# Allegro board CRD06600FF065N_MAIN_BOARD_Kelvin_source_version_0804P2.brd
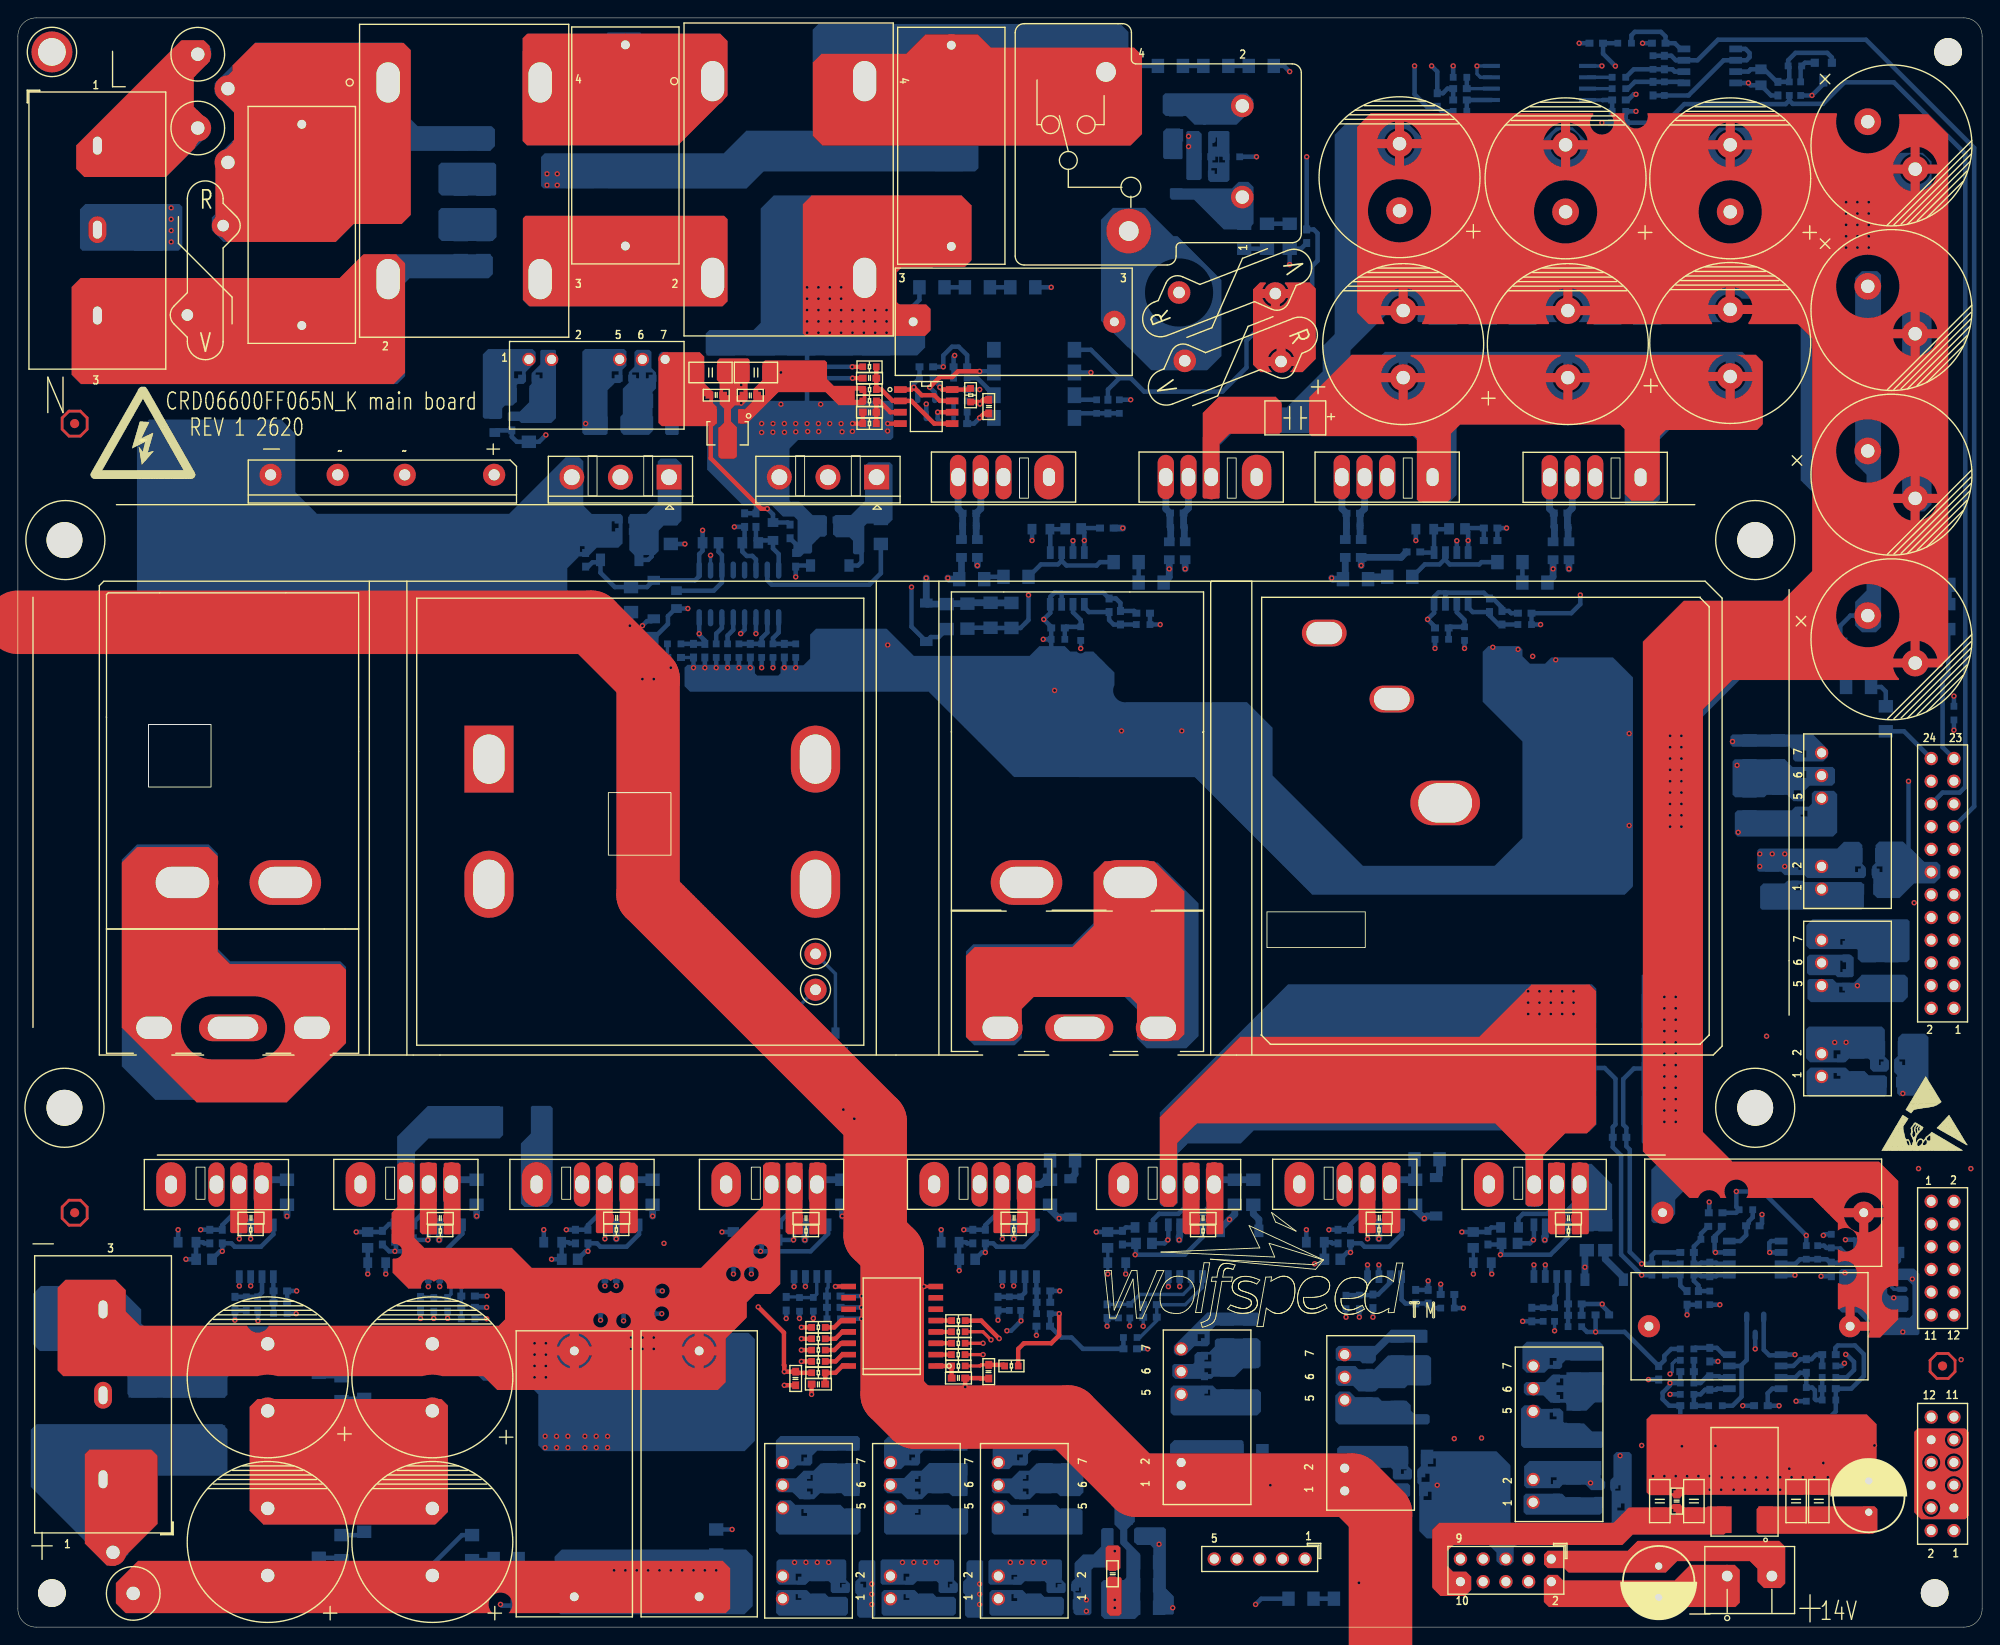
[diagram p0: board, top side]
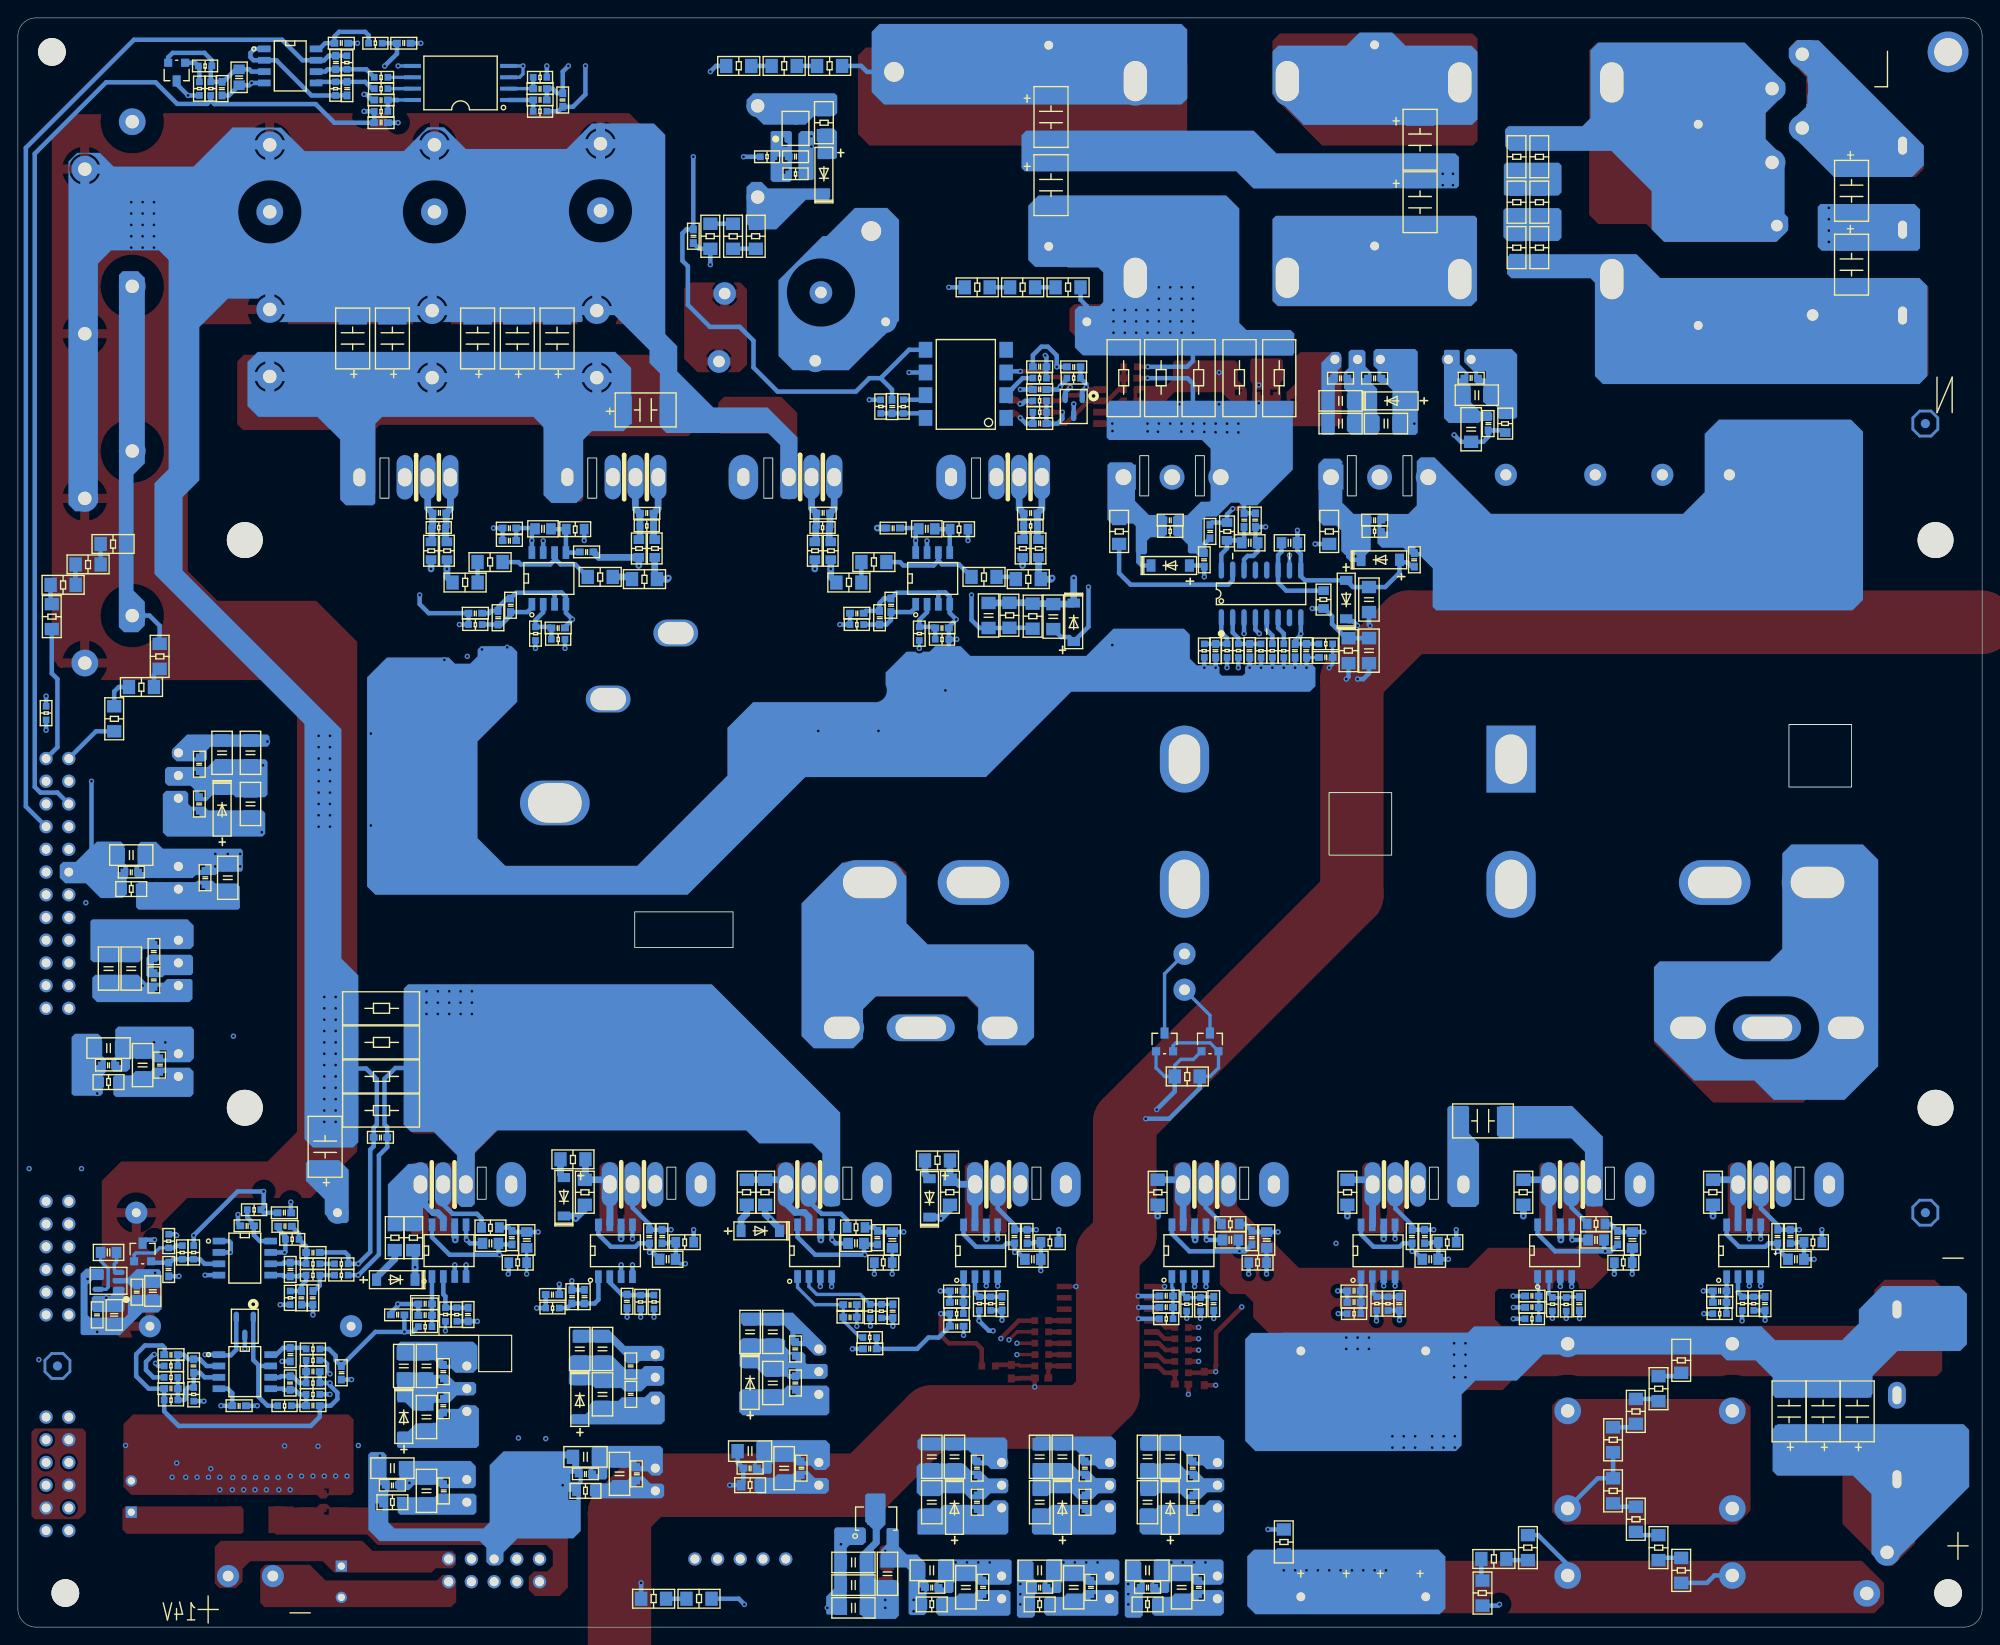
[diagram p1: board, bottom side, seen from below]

Outline 219.69 x 180 mm; copper layers: TOP, ART02, ART03, GND04, ART05, BOTTOM. Coordinates in mm from the lower left corner of the outline.
Outline path: rectangle 14.61,93.97 21.6,100.97 ; rectangle 19.93,47.85 20.93,51.45 ; rectangle 41.14,47.85 42.14,51.45 ; rectangle 60.82,47.85 61.82,51.45 ; rectangle 63.78,126.53 64.78,131.03 ; rectangle 66.04,86.35 73.04,93.34 ; rectangle 70,126.53 71,131.03 ; rectangle 82.03,47.85 83.03,51.45 ; rectangle 86.99,126.53 87.99,131.03 ; rectangle 93.21,126.53 94.21,131.03 ; rectangle 105.27,47.85 106.27,51.45 ; rectangle 112.02,126.27 113.02,130.77 ; rectangle 126.42,47.85 127.42,51.45 ; rectangle 135.26,126.27 136.26,130.77 ; rectangle 139.7,76.01 150.7,80.01 ; rectangle 146.1,47.85 147.1,51.45 ; rectangle 154.95,126.27 155.95,130.77 ; rectangle 167.31,47.85 168.31,51.45 ; rectangle 178.19,126.27 179.19,130.77 ; 0,177.97 arc(0.6,179.4) 2.03,180 217.66,180 arc(219.09,179.4) 219.69,177.97 219.69,2.03 arc(219.09,0.6) 217.66,0 2.03,0 arc(0.6,0.6) 0,2.03 0,177.97

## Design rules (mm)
net group CLAMPQ8: nets CLAMPQ8 DRVSA
net group N: nets N N15816850
net group N17259967: nets N17259967 N17259969
net group PFCDRVB: nets N17381677 PFCDRVB
net group PWM1B: nets N17750019 PWM1B
net group AC_L_SAMP: nets AC_L_SAMP AC_L_SAMP_D N17244938 N17244999
net group IPFC: nets IPFC N17245029 N17245032
net group N17259772: nets N17259772 N17259775 N17259778
net group PFC_G_A: nets N10486979 N16587331 N16587391 PFC_G_A

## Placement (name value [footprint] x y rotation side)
C1  0.1uF  [C0603]  144.15 155.57 90 bottom
C6  1n  [C0603]  149.35 124.59 0 bottom
C7  1n  [C0603]  172.55 124.61 0 bottom
C8  1n  [C0603]  90.81 123.83 180 bottom
C9  180uF  [ECAP_D18P7_5]  173.35 143.51 0 top
C10  180uF  [ECAP_D18P7_5]  154.53 162.18 0 top
C11  450V 180uF  [ECAP_D18P7_5]  173.1 162.05 0 top
C12  180uF  [ECAP_D18P7_5]  154.94 143.51 0 top
C13  180uF  [ECAP_D18P7_5]  209.55 110.49 225 top
C14  180uF  [ECAP_D18P7_5]  209.55 147.32 225 top
C15  180uF  [ECAP_D18P7_5]  191.52 162.05 0 top
C16  180uF  [ECAP_D18P7_5]  209.55 165.74 225 top
C17  180uF  [ECAP_D18P7_5]  209.55 128.91 225 top
C18  180uF  [ECAP_D18P7_5]  191.52 143.64 0 top
C23  1n  [C0603]  106.43 124.59 0 bottom
C24  1n  [C0603]  67.94 123.83 180 bottom
C25  1n  [C0603]  129.62 124.61 0 bottom
C26  0.1u  [C0603]  183.51 177.16 0 bottom
C27  0.1u  [C0603]  179.07 170.81 180 bottom
C28  DNP  [C0603]  182.88 172.09 90 bottom
C29  0.1u  [C0603]  161.29 170.81 0 bottom
C30  0.01u  [C0603]  161.29 172.09 180 bottom
C31  DNP  [C0603]  184.15 175.01 90 bottom
C33  2.2u  [C0805]  81.92 121.28 180 bottom
C34  10u  [C1206]  68.58 109.22 270 bottom
C35  0.33n  [C0603]  85.72 109.22 270 bottom
C36  0.33n  [C0603]  81.92 109.22 270 bottom
C37  10u  [C1206]  68.58 114.94 90 bottom
C38  2.2u  [C0805]  77.47 121.28 180 bottom
C39  1u  [C0603]  76.83 109.22 270 bottom
C40  0.1u  [C0603]  75.56 109.22 270 bottom
C41  2.2u  [C0805]  160.96 122.85 0 bottom
C42  10u  [C1206]  111.12 113.16 90 bottom
C43  0.33n  [C0603]  159.26 111.76 180 bottom
C44  0.33n  [C0603]  116.33 111.76 180 bottom
C45  10u  [C1206]  103.89 113.03 270 bottom
C46  2.2u  [C0805]  118.03 122.85 0 bottom
C47  1u  [C0603]  123.32 112.9 90 bottom
C48  0.1u  [C0603]  122.05 114.3 90 bottom
C53  1n  [C0603]  26.07 45.75 180 top
C54  1n  [C0603]  66.97 45.75 180 top
C55  470uF250V  [ECAP_D18P7_5]  27.94 9.53 0 top
C56  1n  [C0603]  111.42 45.75 180 top
C57  1n  [C0603]  152.26 45.75 180 top
C58  470uF250V  [ECAP_D18P7_5]  46.35 9.53 0 top
C59  0.1u  [C1812]  55.82 56.62 180 bottom
C63  5u  [CAPFILM_31_5X12_5MM]  62.23 17.14 90 top
C66  5u  [CAPFILM_31_5X12_5MM]  76.2 17.14 90 top
C72  470uF250V  [ECAP_D18P7_5]  27.94 27.94 0 top
C76  1n  [C0603]  47.24 45.72 180 top
C77  1n  [C0603]  88.15 45.72 180 top
C78  470uF250V  [ECAP_D18P7_5]  46.35 27.94 0 top
C79  1n  [C0603]  132.55 45.72 180 top
C80  1n  [C0603]  173.42 45.72 180 top
C81  1u  [C0603]  179.14 54.79 180 bottom
C82  0.47n  [C0603]  186.69 24.77 0 bottom
C83  0.12n  [C0603]  189.23 27.3 270 bottom
C84  0.1u  [C0603]  194.05 44.89 180 bottom
C87  0.12n  [C0603]  186.69 28.57 0 bottom
C88  0.1u  [C0603]  194.94 24.77 180 bottom
C89  2.2n  [C0603]  186.69 36.83 270 bottom
C90  nc  [C0603]  187.96 36.83 270 bottom
C91  0.12n  [C0603]  189.23 40.01 90 bottom
C92  0.12n  [C0603]  202.56 26.67 0 bottom
C93  1n  [C0603]  202.82 40.01 270 bottom
C94  0.12n  [C0603]  189.81 44.82 0 bottom
C96  nc  [C0603]  186.69 41.91 180 bottom
C97  0.12n  [C0603]  200.03 29.21 270 bottom
C99  0.47n  [C0603]  202.56 30.48 180 bottom
C100  0u1  [C0603]  87 27.81 270 top
C101  0u1  [C0603]  108.58 28.57 270 top
C102  0u1  [C0603]  105.2 27.85 180 top
C103  0u1  [C0603]  89.53 27.18 0 top
C136  1uF  [C0603]  204.47 75.56 270 bottom
C137  10uF  [C1206]  209.55 64.77 180 bottom
C138  1uF  [C0603]  209.55 62.87 180 bottom
C139  0u1  [C0603]  203.84 62.87 90 bottom
C140  2u2  [C1206]  205.74 62.87 90 bottom
C141  10uF  [C1206]  207.01 73.66 270 bottom
C142  1uF  [C0603]  204.47 72.39 270 bottom
C143  10uF  [C1206]  209.55 73.66 270 bottom
C144  10u  [C1206]  77.47 140.34 180 top
C145  1u  [C0603]  78.11 137.79 180 top
C146  1u  [C1206]  82.55 140.34 0 top
C147  1u  [C0603]  81.92 137.79 0 top
C148  1uF  [C0603]  199.39 96.52 270 bottom
C149  4u7  [C1206]  196.85 97.79 270 bottom
C150  10uF  [C1206]  193.68 97.79 270 bottom
C151  1uF  [C0603]  207.01 84.45 180 bottom
C152  0u1  [C0603]  198.75 83.82 90 bottom
C153  1uF  [C0603]  71.75 139.7 180 bottom
C154  4u7  [C1206]  71.75 137.16 180 bottom
C155  10uF  [C1206]  71.75 134.62 180 bottom
C156  10uF  [C1206]  57.15 133.99 90 bottom
C157  10uF  [C1206]  207.01 86.36 180 bottom
C158  1uF  [C0603]  55.24 134.62 90 bottom
C159  0u1  [C0603]  57.15 139.7 0 bottom
C160  2u2  [C1206]  56.52 137.79 0 bottom
C161  2u2  [C1206]  196.22 83.82 90 bottom
C162  1uF  [C0603]  199.39 92.08 270 bottom
C163  10uF  [C1206]  193.68 92.08 270 bottom
C164  1uF  [C0603]  67.94 139.7 180 bottom
C165  10uF  [C1206]  66.67 134.62 180 bottom
C166  1uF  [C0603]  132.72 31.11 270 bottom
C167  4u7  [C1206]  135.25 33.02 270 bottom
C168  10uF  [C1206]  137.79 33.02 270 bottom
C169  10uF  [C1206]  154.31 31.11 270 bottom
C170  1uF  [C0603]  137.79 17.78 180 bottom
C171  1uF  [C0603]  151.13 29.21 270 bottom
C172  4u7  [C1206]  156.84 31.11 270 bottom
C173  10uF  [C1206]  137.79 19.68 180 bottom
C174  0u1  [C0603]  132.08 17.78 90 bottom
C175  2u2  [C1206]  133.99 17.78 90 bottom
C176  1uF  [C0603]  172.09 28.57 270 bottom
C177  10uF  [C1206]  156.21 19.05 180 bottom
C178  1uF  [C0603]  156.21 17.14 180 bottom
C179  0u1  [C0603]  150.5 17.14 90 bottom
C180  2u2  [C1206]  152.4 17.14 90 bottom
C181  10uF  [C1206]  177.8 17.78 180 bottom
C182  1uF  [C0603]  177.8 15.88 180 bottom
C183  0u1  [C0603]  172.09 15.24 90 bottom
C184  2u2  [C1206]  173.99 15.24 90 bottom
C186  1uF  [C0603]  132.72 27.3 270 bottom
C187  1uF  [C0603]  151.13 26.04 270 bottom
C188  10uF  [C1206]  154.31 26.04 270 bottom
C189  1uF  [C0603]  172.09 24.77 270 bottom
C191  10uF  [C1206]  135.25 27.3 270 bottom
C192  1uF  [C0603]  88.27 17.78 270 bottom
C193  4u7  [C1206]  90.81 19.05 270 bottom
C194  10uF  [C1206]  93.34 19.05 270 bottom
C195  1uF  [C0603]  93.34 4.45 180 bottom
C196  0u1  [C0603]  87.63 4.45 90 bottom
C197  2u2  [C1206]  89.53 4.45 90 bottom
C198  1uF  [C0603]  100.33 17.78 270 bottom
C199  10uF  [C1206]  93.34 6.35 180 bottom
C200  4u7  [C1206]  102.87 19.05 270 bottom
C201  10uF  [C1206]  105.41 19.05 270 bottom
C202  1uF  [C0603]  88.27 13.97 270 bottom
C203  10uF  [C1206]  105.41 6.35 180 bottom
C204  1uF  [C0603]  105.41 4.45 180 bottom
C205  0u1  [C0603]  99.69 4.45 90 bottom
C206  1uF  [C0603]  112.39 17.78 270 bottom
C207  2u2  [C1206]  101.6 4.45 90 bottom
C209  10uF  [C1206]  93.34 13.97 270 bottom
C210  10uF  [C1206]  117.47 6.35 180 bottom
C211  1uF  [C0603]  117.47 4.45 180 bottom
C212  0u1  [C0603]  111.76 4.45 90 bottom
C213  2u2  [C1206]  113.67 4.45 90 bottom
C214  1uF  [C0603]  100.33 13.97 270 bottom
C215  10uF  [C1206]  105.41 13.97 270 bottom
C216  1uF  [C0603]  112.39 13.97 270 bottom
C234  10u  [C1206]  183.64 14.1 270 top
C235  1u  [C0603]  185.55 14.1 270 top
C236  10u  [C1206]  187.45 14.1 270 top
C237  10u  [C1206]  198.88 14.1 270 top
C238  10u  [C1206]  201.42 14.1 270 top
C241  0.1u  [C0603]  210.82 34.92 270 bottom
C242  2.2u  [C0805]  208.91 34.92 270 bottom
C245  2.2u  [C0805]  209.55 41.91 180 bottom
C246  2.2u  [C0805]  204.6 37.59 270 bottom
C247  0.1u  [C0603]  206.38 37.47 270 bottom
C248  0.1u  [C0603]  189.23 30.48 90 bottom
C256  10u  [C1206]  122.43 5.97 90 bottom
C257  1u  [C0603]  122.43 5.97 90 top
C258  1u  [C1206]  126.24 7.24 0 bottom
C260  22u  [C1206]  126.24 2.16 0 bottom
C261  22u  [C1206]  126.24 4.7 0 bottom
C267  0.1u  [C1812]  17.78 24.13 90 bottom
C268  0.1u  [C1812]  13.97 24.13 90 bottom
C269  0.1u  [C1812]  21.59 24.13 90 bottom
C270  0.1u  [C1812]  185.32 53.73 90 bottom
C271  0.1u  [C1812]  159.38 144.15 90 bottom
C272  0.1u  [C1812]  163.83 144.15 90 bottom
C273  0.1u  [C1812]  168.28 144.15 90 bottom
C274  0.1u  [C1812]  177.8 144.15 90 bottom
C275  0.1u  [C1812]  182.25 144.15 90 bottom
C276  0.1u  [C1812]  149.48 136.14 180 bottom
C277  0.1u  [C1812]  142.88 135.25 180 top
C278  0.1n  [C0603]  95.25 135.89 0 top
C279  0.1u  [C0603]  105.41 138.43 0 bottom
C280  0.1n  [C0603]  105.41 134.62 0 bottom
C281  220p  [C0603]  95.25 139.7 180 top
C282  4.7n  [C0603]  101.6 140.97 180 bottom
C284  1n  [C0603]  132.72 164.47 0 bottom
C478  1n  [C0603]  196.85 172.09 270 bottom
C479  10uF  [C1206]  173.99 23.5 270 bottom
C480  10uF  [C1206]  176.53 29.21 270 bottom
C481  4u7  [C1206]  173.99 29.21 270 bottom
C482  10uF  [C1206]  117.47 19.05 270 bottom
C483  10uF  [C1206]  117.47 13.97 270 bottom
C484  4u7  [C1206]  114.94 19.05 270 bottom
C496  1u  [C0603]  81.28 123.83 270 bottom
C497  1u  [C0603]  82.55 123.83 90 bottom
C498  1u  [C0603]  156.08 120.27 180 bottom
C499  1u  [C0603]  164.72 121.54 180 bottom
C524  1u  [C0603]  87 119.38 270 bottom
C525  1u  [C0603]  63.5 119.38 270 bottom
C530  0.1u  [C0603]  164.59 114.3 90 bottom
C531  1u  [C0603]  165.99 112.9 90 bottom
C532  0.1u  [C0603]  114.7 37.6 0 bottom
C533  1u  [C0603]  114.7 36.33 0 bottom
C536  1u  [C0603]  106.81 43.69 90 bottom
C537  1u  [C0603]  108.2 43.69 270 bottom
C540  0.1u  [C0603]  126.62 36.07 180 bottom
C541  1u  [C0603]  126.62 34.67 180 bottom
C542  2.2u  [C0805]  106.17 41.15 0 bottom
C543  0.33n  [C0603]  121.82 35.34 270 bottom
C544  0.33n  [C0603]  109.62 36.18 270 bottom
C545  2.2u  [C0805]  121.88 43.31 90 bottom
C547  1u  [C0603]  123.54 43.56 270 bottom
C549  2.2u  [C0805]  125.95 42.93 180 bottom
C550  0.1u  [C0603]  156.34 36.96 90 bottom
C551  1u  [C0603]  157.73 36.96 90 bottom
C552  1u  [C0603]  149.05 43.69 270 bottom
C553  1u  [C0603]  147.65 43.69 90 bottom
C554  0.1u  [C0603]  174.14 36.15 0 bottom
C555  1u  [C0603]  174.14 34.88 0 bottom
C556  2.2u  [C0805]  147.02 41.15 0 bottom
C557  0.33n  [C0603]  169.33 34.96 270 bottom
C558  0.33n  [C0603]  151.55 36.44 270 bottom
C559  2.2u  [C0805]  162.77 43.31 90 bottom
C561  1u  [C0603]  164.42 43.56 270 bottom
C563  2.2u  [C0805]  166.84 42.93 180 bottom
C564  0.1u  [C0603]  29.36 37.6 0 bottom
C565  1u  [C0603]  29.36 36.33 0 bottom
C566  1u  [C0603]  22.86 43.69 270 bottom
C567  1u  [C0603]  21.46 43.69 90 bottom
C568  0.1u  [C0603]  50.35 37.03 0 bottom
C569  1u  [C0603]  50.35 35.76 0 bottom
C570  2.2u  [C0805]  20.83 41.15 0 bottom
C571  0.33n  [C0603]  45.03 36.18 270 bottom
C572  0.33n  [C0603]  24.28 36.18 270 bottom
C573  2.2u  [C0805]  39.12 43.31 90 bottom
C575  1u  [C0603]  40.77 43.56 270 bottom
C577  2.2u  [C0805]  43.18 43.31 180 bottom
C578  0.1u  [C0603]  70.25 37.6 0 bottom
C579  1u  [C0603]  70.25 36.33 0 bottom
C580  1u  [C0603]  63.75 43.69 270 bottom
C581  1u  [C0603]  62.36 43.69 90 bottom
C582  0.1u  [C0603]  91.25 37.03 0 bottom
C583  1u  [C0603]  91.25 35.76 0 bottom
C584  2.2u  [C0805]  61.72 41.15 0 bottom
C585  0.33n  [C0603]  85.93 36.18 270 bottom
C586  0.33n  [C0603]  65.17 36.18 270 bottom
C587  2.2u  [C0805]  80.02 43.31 90 bottom
C589  1u  [C0603]  81.67 43.56 270 bottom
C591  2.2u  [C0805]  84.08 43.31 180 bottom
C592  2.2u  [C0805]  194.94 173.35 270 bottom
C593  25V 220uF  [ECAP_D8P3_5]  183.51 5.08 270 top
C594  25V 220uF  [ECAP_D8P3_5]  207.01 14.61 90 top
C595  2.2u  [C0603]  176.53 177.16 0 bottom
C596  2.2u  [C0603]  158.75 170.81 270 bottom
C597  2.2u  [C0603]  179.07 168.28 0 bottom
C598  2.2u  [C0603]  73.41 108.46 0 bottom
C599  2.2u  [C0603]  86.36 122.56 90 bottom
C601  2.2u  [C0603]  168.53 113.41 180 bottom
C602  2.2u  [C0603]  125.86 113.41 180 bottom
C603  2.2u  [C0603]  183.51 28.45 90 bottom
C604  2.2u  [C0603]  189.88 46.34 0 bottom
C605  2.2u  [C0603]  114.68 33.66 180 bottom
C606  2.2u  [C0603]  124.41 31.12 0 bottom
C607  2.2u  [C0603]  159.89 37.21 180 bottom
C608  2.2u  [C0603]  177.22 34.92 0 bottom
C610  2.2u  [C0603]  108.58 136.53 90 top
C611  2.2u  [C0603]  105.41 140.97 0 bottom
C612  0.1u  [C0603]  121.92 136.53 90 bottom
C613  1u  [C0603]  164.72 122.94 180 bottom
C614  1u  [C0603]  121.79 122.94 180 bottom
CB6  450V4u7  [CAPFILM_26_5X12MM]  195.2 46.35 0 top
CB7  450V4u7  [CAPFILM_26_5X12MM]  193.68 33.66 0 top
CL1  6Ts  [CM_4P]  49.91 161.78 270 top
CL2  6Ts  [CM_4P]  86.2 161.93 270 top
CON1  CON3  [KF45-3]  8.89 156.21 180 top
CON2  CON3  [KF45-3]  9.53 26.04 0 top
CT11  T1T2  [TH47_CR98]  89.21 71.29 0 top
CT12  T1T2  [TH47_CR98]  89.21 75.3 0 top
D1  1N4148W  [SOD-123]  129.54 162.56 270 bottom
D2  PB3510-E3/45  [PB3510]  40.77 128.14 180 top
D8  BAW56LT1  [SOT23]  194.31 33.66 0 bottom
D47  SBD  [SOD-123]  67.31 119.38 0 bottom
D48  SBD  [SOD-123]  90.81 118.75 0 bottom
D57  SBD  [SOD-123]  117.73 48.01 270 bottom
D58  SBD  [SOD-123]  158.62 48.13 270 bottom
D59  SBD  [SOD-123]  136.65 44.32 180 bottom
D60  SBD  [SOD-123]  177.42 38.86 180 bottom
D61  BAT754S  [SOT-23]  91.44 65.41 180 bottom
D62  BAT754S  [SOT-23]  86.36 65.41 180 bottom
F1  25A  [FULSE]  23.5 172.09 90 top
F2  25A  [FULSE]  23.5 163.83 90 top
F3  25A  [FULSE]  10.64 8.36 255 top
J3  CON24A  [CON_2MM54_12X2]  215.26 83.19 90 top
J4  CON12A  [CON_2MM54_6X2]  215.26 17.14 90 top
J5  CON12A  [CON_2MM54_6X2]  215.26 41.27 270 top
J6  CON2  [CON_5MM_2X1]  193.68 5.71 0 top
J7  CON10A  [CON_2MM54_5X2]  166.43 6.35 180 top
J8  CON5  [CON_2MM54_5X1]  138.89 7.62 180 top
MH1  T1T2  [MTH122]  3.81 176.19 0 top
NOREF  -  []  155.6 33.38 0 top
NOREF#2  #VAL  [unnamed#2]  215.26 29.21 0 top
NOREF#3  #VAL  [unnamed#3]  215.88 176.19 0 top
NOREF#4  #VAL  [unnamed#3]  3.81 3.81 0 top
NOREF#5  -  []  0 3.85 0 top
NOREF#6  -  []  3.99 0 90 top
NOREF#7  #VAL  [unnamed#2]  6.35 134.62 0 top
NOREF#8  -  []  13.97 132.72 0 top
NOREF#9  #VAL  [unnamed#2]  6.35 46.35 0 top
NOREF#10  -  []  0 3.24 0 top
NOREF#11  #VAL  [unnamed#3]  214.38 3.81 0 top
NOREF#12  -  []  18.45 0 90 top
NOREF#13  -  []  213.36 56.52 0 top
NOREF#14  #VAL  [unnamed#2]  215.26 29.21 180 bottom
NOREF#15  #VAL  [unnamed#2]  6.35 134.62 180 bottom
NOREF#16  #VAL  [unnamed#2]  6.35 46.35 180 bottom
Q2  C3M0060065K  [TO-247-4L]  153.15 128.63 180 top
Q3  C3M0060065K  [TO-247-4L]  176.41 128.61 180 top
Q4  C3M0060065D  [TO247]  90.6 128.63 180 top
Q5  C3M0060065D  [TO247]  67.39 128.63 180 top
Q6  C3M0060065K  [TO-247-4L]  110.24 128.64 180 top
Q7  C3M0060065K  [TO-247-4L]  133.46 128.64 180 top
Q8  C3M0060065K  [TO-247-4L]  22.2 49.5 0 top
Q9  C3M0060065K  [TO-247-4L]  63.09 49.52 0 top
Q10  C3M0060065K  [TO-247-4L]  107.56 49.53 0 top
Q11  C3M0060065K  [TO-247-4L]  148.4 49.53 0 top
Q12  C3M0060065K  [TO-247-4L]  43.39 49.52 0 top
Q13  C3M0060065K  [TO-247-4L]  84.29 49.52 0 top
Q14  C3M0060065K  [TO-247-4L]  128.7 49.52 0 top
Q15  C3M0060065K  [TO-247-4L]  169.59 49.52 0 top
Q60  FMMT718/SOT  [SOT23]  101.6 136.53 0 bottom
Q61  FMMT618/SOT  [SOT23]  132.72 167.64 180 bottom
R1  15R  [R1206]  137.16 155.57 270 bottom
R2  15R  [R1206]  139.7 155.57 90 bottom
R3  15R  [R1206]  142.24 155.57 270 bottom
R4  22  [R1206]  129.54 168.28 90 bottom
R5  1K  [R0603]  135.89 164.47 0 bottom
R6  360K  [R1206]  52.07 164.47 90 bottom
R7  360K  [R1206]  49.53 164.47 90 bottom
R8  10k  [R0603]  132.72 162.56 180 bottom
R9  360K  [R1206]  52.07 159.38 90 bottom
R10  360K  [R1206]  49.53 159.38 90 bottom
R11  360K  [R1206]  49.53 154.31 90 bottom
R12  360K  [R1206]  52.07 154.31 90 bottom
R14  1M  [R1206]  128.91 174.62 0 bottom
R15  1M  [R1206]  133.99 174.62 0 bottom
R16  1M  [R1206]  139.06 174.62 0 bottom
R20  1M  [R1206]  102.23 149.86 0 bottom
R21  1M  [R1206]  107.31 149.86 0 bottom
R22  1M  [R1206]  112.39 149.86 0 bottom
R27  5.6R  [R1206]  154.56 117.47 180 bottom
R28  5.6R  [R1206]  166.88 119.13 0 bottom
R29  100R  [R1206]  96.52 122.56 90 bottom
R30  0R  [R1206]  209.04 121.16 180 bottom
R31  10k  [R0603]  149.35 123.19 180 bottom
R32  10k  [R0603]  172.62 123 180 bottom
R33  10k  [R0603]  90.81 122.56 0 bottom
R34  1R  [R0805]  150.24 120.65 90 bottom
R35  1R  [R0805]  173.48 120.4 90 bottom
R37  470K  [R1206]  211.84 118.87 180 bottom
R38  470K  [R1206]  203.84 108.58 90 bottom
R39  470K  [R1206]  214.63 116.59 180 bottom
R40  470K  [R1206]  205.87 105.16 180 bottom
R41  8m  [R2512]  96.01 139.7 270 bottom
R42  8m  [R2512]  91.82 139.7 270 bottom
R43  470K  [R1206]  215.9 113.03 90 bottom
R44  8m  [R2512]  87.63 139.7 270 bottom
R45  470K  [R1206]  208.91 101.6 90 bottom
R46  8m  [R2512]  83.06 139.7 270 bottom
R47  8m  [R2512]  78.61 139.7 270 bottom
R48  100R  [R1206]  73.03 122.56 90 bottom
R51  5.6R  [R1206]  111.63 117.47 180 bottom
R52  5.6R  [R1206]  123.95 119.13 0 bottom
R53  10k  [R0603]  106.43 123.19 180 bottom
R54  10k  [R0603]  67.94 122.56 0 bottom
R55  10k  [R0603]  129.69 123 180 bottom
R56  1R  [R0805]  107.31 120.65 90 bottom
R60  1R  [R0805]  130.56 120.4 90 bottom
R62  68R  [R0603]  161.29 173.35 180 bottom
R63  2.4k  [R0603]  179.07 172.09 180 bottom
R64  2.4k  [R0603]  179.07 173.35 180 bottom
R65  3.3k  [R0603]  182.88 175.01 270 bottom
R66  3.3k  [R1206]  70.87 109.22 270 bottom
R67  4.7K  [R0603]  87 109.22 270 bottom
R68  4.7K  [R0603]  80.64 109.22 270 bottom
R69  1K  [R0603]  79.38 109.22 270 bottom
R70  NC  [R0603]  78.11 109.22 270 bottom
R71  100  [R0603]  161.8 111.12 90 bottom
R72  4.7K  [R0603]  159.26 110.49 180 bottom
R73  4.7K  [R0603]  116.33 110.49 180 bottom
R74  100  [R0603]  118.87 111.12 90 bottom
R75  2.2k  [R1206]  108.79 113.18 90 bottom
R78  10R  [R1206]  30.1 48.64 270 bottom
R79  10R  [R1206]  70.99 48.64 90 bottom
R80  10R  [R1206]  115.44 48.64 270 bottom
R81  10R  [R1206]  156.29 48.64 90 bottom
R82  10k  [R0603]  26.04 44.45 0 top
R83  10k  [R0603]  66.93 44.45 0 top
R84  510k  [R1206]  33.66 6.35 90 bottom
R85  10k  [R0603]  111.38 44.45 0 top
R86  10k  [R0603]  152.22 44.45 0 top
R89  510k  [R1206]  36.2 8.89 90 bottom
R90  510k  [R1206]  38.73 12.06 90 bottom
R93  510k  [R1206]  41.27 15.24 90 bottom
R94  9R1  [R1206]  51.31 48.64 270 bottom
R95  9R1  [R1206]  92.21 48.64 90 bottom
R96  510k  [R1206]  41.27 20.95 90 bottom
R97  9R1  [R1206]  136.11 48.64 270 bottom
R98  9R1  [R1206]  175.47 43.56 90 bottom
R99  10k  [R0603]  47.24 44.32 0 top
R100  10k  [R0603]  88.15 44.32 0 top
R101  510k  [R1206]  38.73 24.13 90 bottom
R102  510k  [R1206]  36.2 26.67 90 bottom
R103  10k  [R0603]  132.55 44.32 0 top
R104  10k  [R0603]  173.42 44.32 0 top
R107  510k  [R1206]  33.66 29.84 90 bottom
R110  20m  [R2512]  179.07 61.59 0 bottom
R111  20m  [R2512]  179.07 57.78 0 bottom
R112  20m  [R2512]  179.07 65.41 0 bottom
R113  20m  [R2512]  179.07 69.22 0 bottom
R114  470k  [R1206]  78.11 9.53 90 bottom
R115  470k  [R1206]  143.51 3.17 0 bottom
R116  100K  [R0603]  189.87 24.77 180 bottom
R117  1K  [R0603]  186.69 26.04 180 bottom
R118  470k  [R1206]  148.59 3.17 0 bottom
R119  47K  [R0603]  189.23 36.83 90 bottom
R120  1K  [R0603]  183.51 39.37 180 bottom
R121  5.6K  [R0603]  186.69 39.37 180 bottom
R122  15K  [R0603]  186.69 29.84 180 bottom
R123  1.2K  [R0603]  186.69 27.3 180 bottom
R126  200R  [R0603]  200.03 41.91 270 bottom
R127  100K  [R0603]  202.56 27.94 180 bottom
R128  1K  [R0603]  201.29 41.91 270 bottom
R129  1.2K  [R0603]  202.56 25.4 180 bottom
R130  5.6K  [R0603]  186.69 40.64 180 bottom
R132  47K  [R0603]  189.01 43.37 0 bottom
R134  15K  [R0603]  200.03 26.04 270 bottom
R135  1K  [R0603]  183.51 40.64 180 bottom
R136  3.57K  [R0603]  202.82 43.18 270 bottom
R138  1K  [R0603]  202.56 29.21 0 bottom
R139  10R  [R0603]  89.53 28.45 180 top
R140  10R  [R0603]  105.19 29.21 0 top
R141  51R  [R0603]  105.17 30.48 0 top
R142  51R  [R0603]  89.53 29.72 180 top
R143  51R  [R0603]  105.18 31.76 0 top
R144  51R  [R0603]  89.53 30.99 180 top
R145  51R  [R0603]  105.18 33.03 0 top
R146  51R  [R0603]  89.53 32.26 180 top
R147  51R  [R0603]  105.19 34.28 0 top
R148  51R  [R0603]  89.53 33.53 180 top
R181  1R  [R0805]  209.55 60.96 0 bottom
R182  1R  [R0805]  207.01 82.55 0 bottom
R183  1R  [R0805]  53.34 134.62 270 bottom
R184  1R  [R0805]  137.79 15.88 0 bottom
R185  1R  [R0805]  156.21 15.24 0 bottom
R186  1R  [R0805]  177.8 13.97 0 bottom
R187  1R  [R0805]  93.34 2.54 0 bottom
R188  1R  [R0805]  105.41 2.54 0 bottom
R189  1R  [R0805]  117.47 2.54 0 bottom
R216  BEAD  [R1206]  149.61 117.22 180 bottom
R217  BEAD  [R1206]  169.67 116.84 0 bottom
R218  BEAD  [R1206]  126.75 116.84 0 bottom
R219  BEAD  [R1206]  106.68 117.22 180 bottom
R234  DNP  [R1206]  106.2 113.08 90 bottom
R239  1K  [R0603]  101.6 139.7 0 bottom
R240  1.3K  [R0603]  95.25 137.16 180 top
R241  2K  [R0603]  105.41 135.89 180 bottom
R242  720R  [R0603]  105.41 137.16 0 bottom
R243  2K  [R0603]  95.25 134.62 180 top
R244  1K  [R0603]  95.25 140.97 180 top
R245  10k  [R0603]  95.25 138.43 0 top
R246  330R  [R0603]  105.41 139.7 0 bottom
R247  NC  [R0603]  120.65 136.53 270 bottom
R248  100  [R0603]  216.53 102.23 90 bottom
R250  100  [R0603]  83.19 109.22 90 bottom
R251  100  [R0603]  84.45 109.22 90 bottom
R537  3.3k  [R0603]  184.15 172.09 270 bottom
R538  1K  [R0603]  198.75 174.62 180 bottom
R539  3.57K  [R0603]  199.39 172.09 90 bottom
R540  200R  [R0603]  198.12 172.09 90 bottom
R541  1R  [R0805]  125.95 44.7 0 bottom
R542  1R  [R0805]  166.84 44.7 180 bottom
R543  1R  [R0805]  43.18 45.09 0 bottom
R544  1R  [R0805]  84.08 45.09 180 bottom
R545  10R  [R0603]  111.12 29.21 180 top
R548  4.7K  [R0603]  123.09 35.34 270 bottom
R549  200  [R0603]  124.36 35.34 90 bottom
R550  4.7K  [R0603]  110.89 36.18 270 bottom
R551  200  [R0603]  112.16 36.18 90 bottom
R552  4.7K  [R0603]  170.6 34.96 270 bottom
R553  200  [R0603]  171.87 34.96 90 bottom
R554  4.7K  [R0603]  150.04 36.38 270 bottom
R555  200  [R0603]  148.54 36.37 90 bottom
R556  4.7K  [R0603]  46.52 36.1 270 bottom
R557  200  [R0603]  48.06 36.11 90 bottom
R558  4.7K  [R0603]  25.55 36.18 270 bottom
R559  200  [R0603]  26.82 36.18 90 bottom
R560  4.7K  [R0603]  87.42 36.1 270 bottom
R561  200  [R0603]  88.97 36.11 90 bottom
R562  200  [R0603]  67.71 36.18 90 bottom
R563  4.7K  [R0603]  66.44 36.18 270 bottom
R564  4.3R  [R1206]  116.84 52.2 0 bottom
R565  4.3R  [R1206]  157.61 52.32 180 bottom
R566  3.6R  [R1206]  138.18 48.64 270 bottom
R567  3.6R  [R1206]  177.54 43.56 90 bottom
R568  NC  [R1206]  88.9 61.59 180 bottom
R569  470k  [R1206]  54.61 7.62 0 bottom
R570  470k  [R1206]  55.88 3.81 270 bottom
R571  470k  [R1206]  50.8 8.89 270 bottom
R572  10R  [R0603]  179.71 177.16 0 bottom
R573  10R  [R0603]  161.29 169.54 0 bottom
R574  10R  [R0603]  179.07 169.54 180 bottom
R575  10R  [R0603]  73.41 109.98 0 bottom
R576  10R  [R0805]  84.45 122.56 90 bottom
R577  10R  [R0805]  73.66 114.94 270 bottom
R578  10R  [R0603]  168.53 112.14 180 bottom
R579  10R  [R0603]  125.86 112.14 180 bottom
R580  1R  [R0805]  157.35 122.81 180 bottom
R581  1R  [R0805]  114.43 122.81 180 bottom
R582  10R  [R0603]  186.69 31.11 180 bottom
R583  10R  [R0603]  193.27 46.69 180 bottom
R584  10R  [R0603]  114.7 35.06 180 bottom
R585  10R  [R0603]  124.41 32.39 0 bottom
R586  10R  [R0603]  159.89 35.69 180 bottom
R587  10R  [R0603]  174.14 33.61 180 bottom
R588  1R  [R0805]  163.79 40.77 0 bottom
R589  1R  [R0805]  145.11 43.05 180 bottom
R590  1R  [R0805]  122.9 40.77 0 bottom
R591  1R  [R0805]  104.27 43.05 180 bottom
R592  1R  [R0805]  18.92 43.05 180 bottom
R593  1R  [R0805]  40.13 40.77 0 bottom
R594  1R  [R0805]  59.82 43.05 180 bottom
R595  1R  [R0805]  81.03 40.77 0 bottom
R596  10R  [R0603]  106.55 137.79 90 top
R597  10R  [R0603]  123.19 136.53 90 bottom
R598  10R  [R0603]  29.36 35.06 180 bottom
R599  10R  [R0603]  50.35 34.49 180 bottom
R600  10R  [R0603]  70.25 35.06 180 bottom
R601  10R  [R0603]  91.25 34.49 180 bottom
R602  2.2R  [R0805]  148.46 120.65 90 bottom
R603  2.2R  [R0805]  128.78 120.4 90 bottom
R604  2.2R  [R0805]  171.7 120.4 90 bottom
R605  2.2R  [R0805]  105.54 120.65 90 bottom
RLY1  832HA-1A-F-C-12VDC  [T9SV1K15-12]  129.32 165.06 90 top
RV1  NTC  [NTC_OD20MM]  135.25 149.22 201.2 top
RV2  NTC  [NTC_OD20MM]  135.89 141.6 21.4 top
T1  HEATSINK including PFC choke, Transformer and resonant tanks of CLLC  [HEATSINK20]  194.31 58.09 180 top
U2  OPA2376  [SOIC8]  189.23 174.62 180 bottom
U3  LM2904  [SOIC8]  194.31 28.57 180 bottom
U4  OPA2376  [SOIC8]  194.31 41.27 180 bottom
U5  SI8233BB-D-IS1  [SOIC16-127W]  80.64 115.57 90 bottom
U9  AZ431  1.25V  [SOT-23]  205.74 41.91 180 bottom
U10  Si8662  [WB_SOIC16]  97.79 33.66 90 top
U15  R15P21503D  [G1212S_2W11]  203.84 69.22 90 top
U16  MC78L05F-TP  [SOT-89-3L]  79.38 133.99 270 top
U17  R15P21503D  [G1212S_2W11]  203.84 90.17 90 top
U18  R15P21503D  [G1212S_2W11]  64.77 139.7 0 top
U19  R15P21503D  [G1212S_2W11]  132.21 23.5 90 top
U20  R15P21503D  [G1212S_2W11]  150.5 22.86 90 top
U21  R15P21503D  [G1212S_2W11]  171.58 21.59 90 top
U22  R15P21503D  [G1212S_2W11]  87.63 10.79 90 top
U23  R15P21503D  [G1212S_2W11]  99.69 10.79 90 top
U24  R15P21503D  [G1212S_2W11]  111.76 10.79 90 top
U29  LF50ABDT-TR  [TO252AB]  193.17 19.18 0 top
U30  TPS60400  [TSOT23-5]  209.55 38.73 90 bottom
U33  MC78L05F-TP  [SOT-89-3L]  123.7 11.68 90 bottom
U34  LM2903  [SOIC8]  101.6 136.53 0 top
U35  6N136  [SOO8]  113.67 139.06 0 bottom
U55  AZ431  1.25V  [SOT-23]  201.93 173.99 0 bottom
U103  ACPL-C790-000E  [SSO-8]  170.18 172.72 90 bottom
U104  UCC5350MC  [SOIC8]  160.3 117.3 90 bottom
U106  UCC5350MC  [SOIC8]  117.37 117.3 90 bottom
U107  UCC5350MC  [SOIC8]  130.58 42.11 90 bottom
U108  UCC5350MC  [SOIC8]  112.01 42.1 90 bottom
U109  UCC5350MC  [SOIC8]  171.47 42.11 90 bottom
U110  UCC5350MC  [SOIC8]  152.86 42.1 90 bottom
U111  UCC5350MC  [SOIC8]  47.81 42.11 90 bottom
U112  UCC5350MC  [SOIC8]  26.67 42.1 90 bottom
U113  UCC5350MC  [SOIC8]  88.71 42.11 90 bottom
U114  UCC5350MC  [SOIC8]  67.56 42.1 90 bottom
VAR1  S20K460  [MOV_OD21P5MM_PI10MM_PINV3P3MM]  20.95 151.76 90 top
XC2  1uF  [CAPFILM_26_5X12MM]  67.94 165.74 270 top
XC3  1uF  [CAPFILM_26_5X12MM]  104.4 165.69 270 top
XC4  1uF  [CAPFILM_26_5X12MM]  111.38 146.01 180 top
XC5  1uF  [CAPFILM_26_5X12MM]  31.75 156.84 270 top
YC1  2200p  [C1812]  62.87 166.37 270 bottom
YC2  220p  [C1812]  14.61 160.66 270 bottom
YC3  2200p  [C1812]  104.14 168.91 270 bottom
YC4  2200p  [C1812]  62.87 159.38 270 bottom
YC5  220p  [C1812]  14.61 152.4 270 bottom
YC6  2200p  [C1812]  104.14 161.29 270 bottom
ZD13  2V7V  [SOD-123]  71.12 114.94 270 bottom
ZD14  2V7V  [SOD-123]  101.6 112.39 90 bottom
ZD35  3V3  [SOD-123]  196.85 91.44 90 bottom
ZD36  3V3  [SOD-123]  66.04 137.16 0 bottom
ZD37  3V3  [SOD-123]  137.79 27.3 90 bottom
ZD38  3V3  [SOD-123]  156.84 25.4 90 bottom
ZD39  3V3  [SOD-123]  90.81 13.34 90 bottom
ZD40  3V3  [SOD-123]  102.87 13.34 90 bottom
ZD41  3V3  [SOD-123]  176.53 23.5 90 bottom
ZD42  3V3  [SOD-123]  114.94 13.34 90 bottom

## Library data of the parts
C1 C6-C8 C23-C31 C33-C48 C53 C54 C56 C57 C59 C63 C66 C76 C77 C79-C84 C87-C94 C96 C97 C99-C103 C136-C184 C186-C189 C191-C207 C209-C216 C234-C238 C241 C242 C245-C248 C256-C258 C260 C261 C267-C282 C284 C478-C484 C496-C499 C524 C525 C530-C533 C536 C537 C540-C545 C547 C549-C559 C561 C563-C573 C575 C577-C587 C589 C591 C592 C595-C599 C601-C608 C610-C614 CB6 CB7 XC2-XC5 = CAP NP: Tolerance: #TOL; User Part Number: HAMP
C9-C18 C55 C58 C72 C78 C593 C594 = CAP POL: Tolerance: #TOL; User Part Number: HAMP
CL1 CL2 = TRNSFMR 67125450_0: Tolerance: #TOL; User Part Number: HAMP
CON1 CON2 = CON3: Tolerance: #TOL; User Part Number: HAMP
CT11 CT12 MH1 = CON1_2: Tolerance: #TOL; User Part Number: HAMP
D1 = DIODE_0: Tolerance: #TOL; User Part Number: HAMP
D2 = BR805D: Tolerance: #TOL; User Part Number: HAMP
D8 = LED081_200MA_30V_BAT54A_SOT23: Tolerance: #TOL; User Part Number: HAMP
D47 D48 D57-D60 ZD13 ZD14 ZD35-ZD42 = DIODE ZENER_0: Tolerance: #TOL; User Part Number: HAMP
D61 D62 = FMMD6100/SOT_0: Tolerance: #TOL; User Part Number: HAMP
F1-F3 = FUSE_0: Tolerance: #TOL; User Part Number: HAMP
J3 = CON24A: Tolerance: #TOL; User Part Number: HAMP
J4 J5 = CON12A: Tolerance: #TOL; User Part Number: HAMP
J6 = CON2: Tolerance: #TOL; User Part Number: HAMP
J7 = CON10A: Tolerance: #TOL; User Part Number: HAMP
J8 = CON5: Tolerance: #TOL; User Part Number: HAMP
NOREF#2 NOREF#3 NOREF#7 NOREF#9 NOREF#11 NOREF#14-NOREF#16 = -: Tolerance: #TOL; User Part Number: HAMP
NOREF#4 = -: User Part Number: HAMP; Tolerance: #TOL
Q2 Q3 Q6-Q15 = C3M0065090J_4: Tolerance: #TOL; User Part Number: HAMP
Q4 Q5 = MOSFET N: User Part Number: HAMP; Tolerance: #TOL
Q60 = FMMT718/SOT: Tolerance: #TOL; User Part Number: HAMP
Q61 = FMMT618/SOT: Tolerance: #TOL; User Part Number: HAMP
R1-R5 R8 R22 R30 R43-R47 R67-R69 R71 R72 R75 R84 R89 R90 R93 R96 R101 R102 R107 R139-R148 R181-R189 R234 R250 R251 R545 R548-R563 R568 = RESISTOR: Tolerance: #TOL; User Part Number: HAMP
R6 R9 = R_2: Tolerance: #TOL; User Part Number: HAMP
R7 = R_0: Tolerance: #TOL; User Part Number: HAMP
R10 = R_1: Tolerance: #TOL; User Part Number: HAMP
R11 R12 = R_2: Tolerance: #TOL; User Part Number: HAMP; signal model: R_0402_DISCRETE_0.0_B3-RES-0000_0.0
R14-R16 R20 R21 R37-R42 R66 R70 R73 R74 = RESISTOR: Tolerance: #TOL; User Part Number: HAMP; signal model: R_0402_DISCRETE_0.0_B3-RES-0000_0.0
R27-R29 R31 R48 R52-R56 R60 R62-R65 R79-R83 R85 R86 R94 R95 R97-R100 R103 R104 R110-R123 R126-R130 R132 R134-R136 R138 R216-R219 R239-R248 R537-R544 R564-R567 R569-R605 = R: Tolerance: #TOL; User Part Number: HAMP
R32-R35 R51 R78 = R: Tolerance: #TOL; User Part Number: HAMP; signal model: R_0402_DISCRETE_0.0_B3-RES-0000_0.0
RLY1 = RELAY SPST_1: Tolerance: #TOL; User Part Number: HAMP
RV1 RV2 VAR1 = VARISTOR: Tolerance: #TOL; User Part Number: HAMP
T1 = HEATSINK_11: Tolerance: #TOL; User Part Number: HAMP
U2-U4 U34 = LM293A: Tolerance: #TOL; User Part Number: HAMP
U5 = SI8233BB-D-IS1: Tolerance: #TOL; User Part Number: HAMP
U9 U55 = LEU094_ZTL431AFTA_SOT23_0: Tolerance: #TOL; User Part Number: HAMP
U10 = Si8661_3: Tolerance: #TOL; User Part Number: HAMP
U15 U17-U24 = E1212S-2WR2_3: Tolerance: #TOL; User Part Number: HAMP
U16 U33 = MC78L05F-TP: User Part Number: HAMP; Tolerance: #TOL
U29 = MC78L05F-TP: Tolerance: #TOL; User Part Number: HAMP
U30 = E1212S-2WR2_1: Tolerance: #TOL; User Part Number: HAMP
U35 = 1EDI60N12AF-DS_2: Tolerance: #TOL; User Part Number: HAMP
U103 = 1EDI60N12AF-DS_1: Tolerance: #TOL; User Part Number: HAMP
U104 U106-U114 = UCC5350MC: Tolerance: #TOL; User Part Number: HAMP
YC1-YC6 = CAP: Tolerance: #TOL; User Part Number: HAMP

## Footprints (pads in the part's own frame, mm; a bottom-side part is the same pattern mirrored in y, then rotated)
C0603
  rect 0.889x0.787 smd: 1(-0.76,0) 2(0.76,0)
C0805
  rect 1.092x1.27 smd: 1(-0.89,0) 2(0.89,0)
C1206
  rect 1.397x1.6 smd: 1(-1.4,0) 2(1.4,0)
C1812
  rect 1.499x3.2 smd: 1(-2.3,0) 2(2.3,0)
CAPFILM_26_5X12MM
  round 2.489 hole 0.991: 1(-11.25,0) 2(11.25,0)
CAPFILM_31_5X12_5MM
  round 3.505 hole 0.991: 1(-13.75,0) 2(13.75,0)
CM_4P
  oval 5.5x3 hole 4.5x2.6: 1(-11,-8.5) 2(11,-8.5) 3(11,8.5) 4(-11,8.5)
CON_2MM54_5X1
  round 1.499 hole 1.016: 1(-5.08,0) 2(-2.54,0) 3(0,0) 4(2.54,0) 5(5.08,0)
CON_2MM54_5X2
  round 1.499 hole 1.016: 1(-5.08,-1.27) 2(-5.08,1.27) 3(-2.54,-1.27) 4(-2.54,1.27) 5(0,-1.27) 6(0,1.27) 7(2.54,-1.27) 8(2.54,1.27) 9(5.08,-1.27) 10(5.08,1.27)
CON_2MM54_6X2
  round 1.499 hole 0.991: 1(-6.35,-1.27) 2(-6.35,1.27) 3(-3.81,-1.27) 4(-3.81,1.27) 5(-1.27,-1.27) 6(-1.27,1.27) 7(1.27,-1.27) 8(1.27,1.27) 9(3.81,-1.27) 10(3.81,1.27) 11(6.35,-1.27) 12(6.35,1.27)
CON_2MM54_12X2
  round 1.499 hole 0.991: 1(-13.97,-1.27) 2(-13.97,1.27) 3(-11.43,-1.27) 4(-11.43,1.27) 5(-8.89,-1.27) 6(-8.89,1.27) 7(-6.35,-1.27) 8(-6.35,1.27) 9(-3.81,-1.27) 10(-3.81,1.27) 11(-1.27,-1.27) 12(-1.27,1.27) 13(1.27,-1.27) 14(1.27,1.27) 15(3.81,-1.27) 16(3.81,1.27) 17(6.35,-1.27) 18(6.35,1.27) 19(8.89,-1.27) 20(8.89,1.27) 21(11.43,-1.27) 22(11.43,1.27) 23(13.97,-1.27) 24(13.97,1.27)
CON_5MM_2X1
  round 2.489 hole 1.194: 1(-2.5,0) 2(2.5,0)
ECAP_D8P3_5
  rect 1.27x1.27 hole 0.813: 1(-1.75,0)
  round 1.27 hole 0.813: 2(1.75,0)
ECAP_D18P7_5
  round 3 hole 1.5: 1(0,-3.75) 2(0,3.75)
FULSE
  round 2.997 hole 1.499: 1(3.85,3.375) 2(0,0)
G1212S_2W11
  round 1.499 hole 1.016: 1(-7.62,2.1) 2(-5.08,2.1) 5(2.54,2.1) 6(5.08,2.1) 7(7.62,2.1)
HEATSINK20
  round 4.013 hole 4.013 unplated: (0,0) (0,-63.5) (189.1,0) (189.1,-63.5)
  oval 7.8x5 hole 6x4.4: 1(34.675,-34.1)
  oval 5.004x2.997 hole 3.988x2.489: 2(48.2,-53.1) 5(179.076,-8.95) 6(161.423,-8.95) 13(84.427,-8.95) 14(66.774,-8.95) 21(40.64,-45.72)
  oval 8.001x5.004 hole 5.994x3.505: 3(175.9,-25.2) 4(164.4,-25.2) 11(81.5,-25.2) 12(69.9,-25.2)
  oval 5.512x7.493 hole 3.505x5.512: 7(141.625,-25) 9(105.1,-25) 10(105.1,-39)
  rect 5.512x7.493 hole 3.505x5.512: 8(141.625,-39)
  oval 7.62x2.997 hole 5.639x2.489: 19(75.6,-8.95) 20(170.25,-8.95)
KF45-3
  oval 2.007x2.997 hole 0.991x2.007: 1(0,-9.5) 2(0,-0.1) 3(0,9.5)
MOV_OD21P5MM_PI10MM_PINV3P3MM
  round 2.54 hole 1.295: 1(-5,2) 2(5,-2)
MTH122
  round 4.572 hole 3.099: 1(0,0)
NTC_OD20MM
  round 2.54 hole 1.295: 1(-5,2) 2(5,-2)
PB3510
  round 2.489 hole 1.245: 1(-12.5,-0.75) 2(-2.5,-0.75) 3(5,-0.75) 4(12.5,-0.75)
R0603
  rect 0.762x0.762 smd: 1(-0.76,0) 2(0.76,0)
R0805
  rect 0.991x1.194 smd: 1(-1,0) 2(1,0)
R1206
  rect 1.397x1.6 smd: 1(-1.4,0) 2(1.4,0)
R2512
  rect 1.524x3.2 smd: 1(-3.3,0) 2(3.3,0)
SOD-123
  rect 1.02x1.4 smd: 1(-2.15,0) 2(2.15,0)
SOIC8
  rect 1.422x0.762 smd: 1(-2.896,1.905) 2(-2.896,0.635) 3(-2.896,-0.635) 4(-2.896,-1.905) 5(2.896,-1.905) 6(2.896,-0.635) 7(2.896,0.635) 8(2.896,1.905)
SOIC16-127W
  oval 1.93x0.61 smd: 1(-2.665,4.445) 2(-2.665,3.175) 3(-2.665,1.905) 4(-2.665,0.635) 5(-2.665,-0.635) 6(-2.665,-1.905) 7(-2.665,-3.175) 8(-2.665,-4.445) 9(2.665,-4.445) 10(2.665,-3.175) 11(2.665,-1.905) 12(2.665,-0.635) 13(2.665,0.635) 14(2.665,1.905) 15(2.665,3.175) 16(2.665,4.445)
SOO8
  rect 1.524x1.778 smd: 1(-4.505,3.81) 2(-4.505,1.27) 3(-4.505,-1.27) 4(-4.505,-3.81) 5(4.505,-3.81) 6(4.505,-1.27) 7(4.505,1.27) 8(4.505,3.81)
SOT23
  oval 0.61x1.27 smd: 1(-0.95,-1.01) 2(0.95,-1.01) 3(0,1.01)
SOT-23
  rect 0.914x0.914 smd: 1(-0.953,-0.991) 2(0.953,-0.991)
  rect 0.914x1.27 smd: 3(0,1.041)
SOT-89-3L
  rect 3.404x2.007 smd: (1.45,0)
  rect 1.6x0.61 smd: 1(-1.45,1.5) 3(-1.45,-1.5)
  rect 2.007x0.711 smd: 2(-1.25,0)
SSO-8
  rect 0.457x1.905 smd: 1(-1.905,-5.373) 2(-0.635,-5.373) 3(0.635,-5.373) 4(1.905,-5.373) 5(1.905,5.373) 6(0.635,5.373) 7(-0.635,5.373) 8(-1.905,5.373)
T9SV1K15-12
  round 2.54 hole 1.499: 1(-5.1,-7.625) 2(5.1,-7.625)
  round 5.004 hole 2.21: 3(-8.9,5.075) 4(8.9,7.625)
TH47_CR98
  round 2.489 hole 1.194: 1(0,0)
TO247
  rect 2.794x2.794 hole 1.778: 1(-5.44,0)
  round 2.794 hole 1.778: 2(0,0) 3(5.44,0)
TO252AB
  rect 1.6x2.997 smd: 1(2.3,-7.16) 3(-2.3,-7.16)
  rect 6.706x6.706 smd: 2(0,-0.51)
TO-247-4L
  oval 3.302x5.004 hole 1.346x2.007: 1(-5.08,0)
  oval 1.829x4.978 hole 1.524x2.032: 2(0,0) 3(2.54,0) 4(5.08,0)
TSOT23-5
  oval 0.61x1.321 smd: 1(-0.95,-1.145) 2(0,-1.145) 3(0.95,-1.145) 4(0.95,1.145) 5(-0.95,1.145)
unnamed#2
  round 1.016 smd: 1(0,0)
unnamed#3
  round 3.099 hole 3.099 unplated: (0,0)
WB_SOIC16
  rect 0.635x1.651 smd: 1(-4.445,-4.877) 2(-3.175,-4.877) 3(-1.905,-4.877) 4(-0.635,-4.877) 5(0.635,-4.877) 6(1.905,-4.877) 7(3.175,-4.877) 8(4.445,-4.877) 9(4.445,4.877) 10(3.175,4.877) 11(1.905,4.877) 12(0.635,4.877) 13(-0.635,4.877) 14(-1.905,4.877) 15(-3.175,4.877) 16(-4.445,4.877)

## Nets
+5V_A: C146.2 C147.2 C596.2 C610.2 C611.1 R240.2 R242.2 R245.1 R246.1 R573.1 R596.1 U16.1(VOUT)
-3V_PSW1: C37.2 C38.2 C45.2 C46.2 C141.2 C142.2 C143.2 C525.2 C614.2 D47.1(ANODE) U5.9(GNDB) U15.5(-VOUT) U106.8(VEE2) ZD13.1(ANODE) ZD14.1(ANODE)
-3V_PSW2: C41.2 C162.2 C163.2 C499.2 C613.2 U17.5(-VOUT) U104.8(VEE2) ZD35.1(ANODE)
-3V_PSW3: C33.2 C164.2 C165.2 C496.2 C524.2 D48.1(ANODE) U5.14(GNDA) U18.5(-VOUT) ZD36.1(ANODE)
-3V_PSW4: C189.2 C479.2 C547.2 C549.2 C561.2 C563.2 U21.5(-VOUT) U107.8(VEE2) U109.8(VEE2) ZD41.1(ANODE)
-3V_PSW5: C186.2 C191.2 C537.2 C542.2 U19.5(-VOUT) U108.8(VEE2) ZD37.1(ANODE)
-3V_PSW7: C187.2 C188.2 C552.2 C556.2 U20.5(-VOUT) U110.8(VEE2) ZD38.1(ANODE)
-3V_PSW9: C202.2 C209.2 C566.2 C570.2 U22.5(-VOUT) U112.8(VEE2) ZD39.1(ANODE)
-3V_PSW10: C216.2 C483.2 C575.2 C577.2 C589.2 C591.2 U24.5(-VOUT) U111.8(VEE2) U113.8(VEE2) ZD42.1(ANODE)
-3V_PSW11: C214.2 C215.2 C580.2 C584.2 U23.5(-VOUT) U114.8(VEE2) ZD40.1(ANODE)
AGND: C1.2 C26.1 C27.1 C35.2 C36.2 C39.2 C40.2 C43.2 C44.2 C47.2 C48.2 C84.1 C88.2 C93.2 C101.2 C102.1 C137.2 C138.2 C139.2 C140.2 C151.2 C152.2 C156.2 C157.2 C158.2 C159.2 C160.2 C161.2 C170.2 C173.2 C174.2 C175.2 C177.2 C178.2 C179.2 C180.2 C181.2 C182.2 C183.2 C184.2 C234.1 C235.1 C236.1 C237.1 C238.1 C241.2 C242.2 C246.2 C247.2 C248.1 C284.1 C478.2 C530.2 C531.2 C532.2 C533.2 C540.2 C541.2 C543.2 C544.2 C550.2 C551.2 C554.2 C555.2 C557.2 C558.2 C592.2 C594.2 C595.1 C597.1 C598.2 C601.2 C602.2 C603.1 C604.1 C605.2 C606.2 C607.2 C608.2 C612.2 J3.2 J3.3 J3.4 J3.21 J5.6 J5.8 J7.6 J7.9 Q61.2(E) R8.2 R67.2 R68.2 R69.2 R70.2 R72.2 R73.2 R136.1 R539.1 R548.2 R550.2 R552.2 R554.2 U2.4(V-) U4.4(V-) U5.4(GNDI) U9.3(A) U10.8(GND1) U15.2(-VIN) U17.2(-VIN) U18.2(-VIN) U19.2(-VIN) U20.2(-VIN) U21.2(-VIN) U29.2(GND) U30.4(GND) U35.5(GND) U55.3(A) U103.5(GND2) U104.3(IN-) U104.4(GND1) U106.3(IN-) U106.4(GND1) U107.3(IN-) U107.4(GND1) U108.3(IN-) U108.4(GND1) U109.3(IN-) U109.4(GND1) U110.3(IN-) U110.4(GND1)
AGND_N: C8.2 C29.1 C30.2 C144.1 C145.1 C146.1 C147.1 C153.2 C154.2 C155.2 C164.1 C165.1 C278.1 C279.2 C280.2 C281.2 C282.1 C496.1 C497.2 C524.1 C596.1 C599.1 C610.1 C611.2 D2.3(AC IN 2) Q4.3(SOURCE) Q5.2(DRAIN) Q60.3(C) R33.1 R41.2 R42.2 R44.2 R46.2 R47.2 R241.1 R243.2 U16.2(GND) U18.6(COM) U34.4(V-) U103.3(VIN-) U103.4(GND1) ZD36.2(CATHODE)
P6.5V: C234.2 C235.2 C236.2 J7.10 U29.3(VIN)
PGND: C9.2 C10.2 C11.2 C12.2 C13.2 C14.2 C15.2 C16.2 C17.2 C18.2 C24.2 C34.2 C37.1 C81.1 C82.1 C87.1 C89.2 C90.2 C92.2 C96.2 C99.1 C270.2 C271.2 C272.2 C273.2 C274.2 C275.2 C276.2 C277.2 C525.1 CB6.2 CB7.2 D2.4(DC OUT MINUS) Q5.3(SOURCE) Q6.2(S) Q7.2(S) R54.1 R66.2 R110.2 R111.2 R112.2 R113.2 R123.2 R129.1 R135.2 ZD13.2(CATHODE)
SGND: C100.2 C103.1 C195.2 C196.2 C197.2 C199.2 C203.2 C204.2 C205.2 C207.2 C210.2 C211.2 C212.2 C213.2 C256.1 C257.1 C258.1 C260.1 C261.1 C564.2 C565.2 C568.2 C569.2 C571.2 C572.2 C578.2 C579.2 C582.2 C583.2 C585.2 C586.2 J4.3 J4.6 J4.10 J8.5 R556.2 R558.2 R560.2 R563.2 U10.9(GND2) U22.2(-VIN) U23.2(-VIN) U24.2(-VIN) U33.2(GND) U111.3(IN-) U111.4(GND1) U112.3(IN-) U112.4(GND1) U113.3(IN-) U113.4(GND1) U114.3(IN-) U114.4(GND1)
_PFCREF1.6V: C28.1 R537.2 U2.1(OUT) U2.2(-IN)
_PREF1.6V: R119.1 U4.1(OUT) U4.2(-IN)
AC_L: D2.2(AC IN 1) RLY1.3(COMMON) RV2.1 T1.21(AC_L_) XC4.1
AC_L_SAMP: CL2.4(P12) R14.1 RLY1.4(NO) RV1.2 XC3.1 YC3.1
AC_L_SAMP_D: J3.10 R16.2
AC_N_D: J3.12 R22.2
ACL1: CL1.4(P12) CL2.1(P11) XC2.1 YC1.1
ACN1: CL1.3(P22) CL2.2(P21) XC2.2 YC4.2
AD_DC_CUR: C94.2 J3.16 R132.2 U4.7(OUT)
CAN5V_GND: J4.2 J8.2
CAN_5V: J4.4 J8.1
CLAMPA: R216.2 R217.2 R602.1 R604.1 U104.7(CLAMP)
CLAMPB: R218.2 R219.2 R603.1 R605.1 U106.7(CLAMP)
CLAMPQ8: C53.1 Q8.4(G) R78.1 R82.2 U112.7(CLAMP)
CLAMPQ9: C54.1 Q9.4(G) R79.2 R83.2 U114.7(CLAMP)
CLAMPQ10: C56.1 Q10.4(G) R80.1 R85.2 R564.1 U108.7(CLAMP)
CLAMPQ11: C57.1 Q11.4(G) R81.2 R86.2 R565.2 U110.7(CLAMP)
CLAMPQ12: C76.1 Q12.4(G) R94.1 R99.2 U111.7(CLAMP)
CLAMPQ13: C77.1 Q13.4(G) R95.2 R100.2 U113.7(CLAMP)
CLAMPQ14: C79.1 Q14.4(G) R97.1 R103.2 R566.1 U107.7(CLAMP)
CLAMPQ15: C80.1 Q15.4(G) R98.2 R104.2 R567.2 U109.7(CLAMP)
DC_14V_INPUT: C593.1 J6.2 J7.1
DCOCP: D8.3 J3.18
DCPWM1A_1H: J5.4 R551.1
DCPWM1A_1L: J5.2 R549.1
DCPWM2A_2H: J5.7 R555.1
DCPWM2A_2L: J5.5 R553.1
DRV_L_G: C176.2 C189.1 C479.1 C480.2 C481.2 C545.2 C547.1 C559.2 C561.1 R541.1 R542.2 U21.6(COM) ZD41.2(CATHODE)
DRVA: D57.2(CATHODE) R80.2 U108.6(OUT)
DRVA_G: C56.2 C166.2 C167.2 C168.2 C186.1 C191.1 C536.2 C537.1 Q10.3(GS) R85.1 U19.6(COM) ZD37.2(CATHODE)
DRVB: D59.2(CATHODE) R97.2 U107.6(OUT)
DRVC: D58.2(CATHODE) R81.1 U110.6(OUT)
DRVC_G: C57.2 C169.2 C171.2 C172.2 C187.1 C188.1 C552.1 C553.2 Q11.3(GS) R86.1 U20.6(COM) ZD38.2(CATHODE)
DRVD: D60.2(CATHODE) R98.1 U109.6(OUT)
DRVSA: R78.2 U112.6(OUT)
DRVSB: R94.2 U111.6(OUT)
DRVSC: R79.1 U114.6(OUT)
DRVSD: R95.1 U113.6(OUT)
EARTH: CON1.2 MH1.1 YC1.2 YC2.2 YC3.2 YC4.1 YC5.1 YC6.1
HM1: Q10.2(S) Q14.1(D) T1.9(T_PRI_1)
HM2: Q11.2(S) Q15.1(D) T1.19(CR_PRI_3)
HM3: Q8.2(S) Q12.1(D) T1.7(T_SEC_2)
HM4: Q9.2(S) Q13.1(D) T1.20(CR_SEC_3)
IGND: C593.2 J6.1 J7.2
IPFC: CL2.3(P22) R20.1 R41.1 R42.1 R44.1 R46.1 R47.1 R62.2 R244.2 XC3.2 XC4.2 YC6.2
IPFCSAMPLE: C31.2 J3.17 R65.1 U2.7(OUT)
L: CON1.1 F1.1 F2.1 YC2.1
N: CL1.2(P21) CON1.3 R11.1 R12.1 VAR1.1 XC5.2 YC5.2
PCS+: C81.2 Q14.2(S) Q15.2(S) R110.1 R111.1 R112.1 R113.1 R117.2 R120.2 R138.2
PFC-FB: J3.23 R43.1
PFC-VO: J3.24 R45.1
PFC_G_A: C148.2 C149.2 C150.2 C162.1 C163.1 C498.2 C499.1 C613.1 R34.1 R35.1 U17.6(COM) ZD35.2(CATHODE)
PFC_G_B: C42.2 C45.1 C614.1 R56.1 R60.1 R75.2 R234.2 ZD14.2(CATHODE)
PFC_L: Q2.2(S) Q3.2(S) Q6.1(D) Q7.1(D) T1.2(LPFC_2)
PFC_OCP: J3.15 R248.1
PFCDRVA: R27.1 R28.1 U104.6(OUT)
PFCDRVB: R51.1 R52.1 U106.6(OUT)
PFCDRVC: R29.1 U5.15(VOA)
PFCDRVD: R48.1 U5.10(VOB)
PFCREF1.6V: C478.1 C592.1 R538.2 R540.2 U2.3(+IN) U55.2(K)
PREF1.6V: C93.1 R126.2 R128.2 U4.3(+IN) U9.2(K)
PWM1A: J3.11 R71.1
PWM1B: J3.5 R74.1
PWM1C: J3.7 R251.1
PWM1D: J3.9 R250.1
RLYCTRL1: J3.22 R5.2
SPGND: C59.2 C63.2 C66.2 C72.2 C78.2 C267.2 C268.2 C269.2 CON2.3 Q12.2(S) Q13.2(S) R107.2
SR-PWM-A: J5.9 R141.2
SR-PWM-A-S: R142.2 R559.1
SR-PWM-B: J5.10 R143.2
SR-PWM-B-S: R144.2 R557.1
SR-PWM-C: J5.11 R145.2
SR-PWM-C-S: R146.2 R562.1
SR-PWM-D: J5.12 R147.2
SR-PWM-D-S: R148.2 R561.1
SR_DETA_PRI: D61.2(C2) D62.2(C2) J5.1 R568.2
SR_DETB_PRI: D61.1(C1) D62.1(C1) J5.3 R568.1
SR_L_G: C206.2 C216.1 C482.2 C483.1 C484.2 C573.2 C575.1 C587.2 C589.1 R543.1 R544.2 U24.6(COM) ZD42.2(CATHODE)
SRA_G: C53.2 C192.2 C193.2 C194.2 C202.1 C209.1 C566.1 C567.2 Q8.3(GS) R82.1 U22.6(COM) ZD39.2(CATHODE)
SRC_G: C54.2 C198.2 C200.2 C201.2 C214.1 C215.1 C580.1 C581.2 Q9.3(GS) R83.1 U23.6(COM) ZD40.2(CATHODE)
VDCLOW+15V: C176.1 C480.1 C481.1 R588.2 R590.2 U21.7(+VOUT)
VLOW+15V: C34.1 C42.1 C136.1 C141.1 C143.1 R66.1 R75.1 R234.1 R577.2 R581.2 U15.7(+VOUT)
VO1+: J4.11 R570.2
VO2+: J4.8 R118.2
VO+: C55.1 C58.1 C59.1 C63.1 C66.1 F3.1 Q8.1(D) Q9.1(D) R84.1 R114.1 R571.1
VP+5V: C237.2 C238.2 C246.1 C247.1 C594.1 C595.2 C597.2 C598.1 C601.1 C602.1 C603.2 C604.2 C605.1 C606.1 C607.1 C608.1 J3.20 R126.1 R134.2 R540.1 R545.1 R572.1 R574.1 R575.1 R578.1 R579.1 R582.2 R583.2 R584.1 R585.1 R586.1 R587.1 R597.2 U29.1(VOUT) U30.2(IN)
VP+15V: C1.1 C137.1 C138.1 C151.1 C156.1 C157.1 C158.1 C170.1 C173.1 C177.1 C178.1 C181.1 C182.1 J3.14 J7.5 R3.2 R181.2 R182.2 R183.2 R184.2 R185.2 R186.2
VP+15V_DCDCA: C166.1 C167.1 C168.1 R591.2 U19.7(+VOUT)
VP+15V_DCDCB: C169.1 C171.1 C172.1 R589.2 U20.7(+VOUT)
VP+15V_HF_PFC: C148.1 C149.1 C150.1 R580.2 U17.7(+VOUT)
VP-5V: C88.1 C241.1 C242.1 J3.19 R122.2 U3.4(V-) U30.1(OUT)
VPFC: C9.1 C10.1 C11.1 C12.1 C13.1 C14.1 C15.1 C16.1 C17.1 C18.1 C270.1 C271.1 C272.1 C273.1 C274.1 C275.1 C276.1 C277.1 CB6.1 CB7.1 D2.1(DC OUT PLUS) Q2.1(D) Q3.1(D) Q4.2(DRAIN) Q10.1(D) Q11.1(D) R30.2 R38.2
VPFC_LF+15V: C144.2 C145.2 C153.1 C154.1 C155.1 C599.2 R576.2 U16.3(VIN) U18.7(+VOUT)
VS+5V: C100.1 C258.2 C260.2 C261.2 J4.7 R139.2 R598.1 R599.1 R600.1 R601.1 U33.1(VOUT)
VS+15V: C195.1 C199.1 C203.1 C204.1 C210.1 C211.1 C256.2 C257.2 J4.1 J8.4 R187.2 R188.2 R189.2 U33.3(VIN)
VS+15V_DCDCA: C192.1 C193.1 C194.1 R592.2 U22.7(+VOUT)
VS+15V_DCDCB: C198.1 C200.1 C201.1 R594.2 U23.7(+VOUT)
VSLOW+15V: C206.1 C482.1 C484.1 R593.2 R595.2 U24.7(+VOUT)
N10486979: C6.2 Q2.3(GS) R31.1 R34.2
N10631533: C6.1 Q2.4(G) R31.2 R602.2
N15409465: CL1.1(P11) F1.2 F2.2 R6.2 R7.2 VAR1.2 XC5.1
N15414859: D1.2(K) R1.1 RLY1.1(COIL2)
N15414880: Q61.3(C) R4.2 RLY1.2(COIL1)
N15816850: R9.1 R10.1 R11.2 R12.2
N15816858: R6.1 R7.1 R9.2 R10.2
N16123691: C267.1 C268.1 C269.1 CON2.1 F3.2
N16148248: R84.2 R89.1
N16148380: C55.2 C58.2 C72.1 C78.1 R93.2 R96.1
N16148534: R90.2 R93.1
N16148538: R89.2 R90.1
N16148540: R96.2 R101.1
N16148544: R102.2 R107.1
N16320789: R101.2 R102.1
N16587331: C7.2 Q3.3(GS) R32.1 R35.2
N16587391: C7.1 Q3.4(G) R32.2 R604.2
N16589757: C25.2 Q7.3(GS) R55.1 R60.2
N16589837: C25.1 Q7.4(G) R55.2 R603.2
N16589901: C23.2 Q6.3(GS) R53.1 R56.2
N16589961: C23.1 Q6.4(G) R53.2 R605.2
N16599678: C8.1 D48.2(CATHODE) Q4.1(GATE) R29.2 R33.2
N16600162: C24.1 D47.2(CATHODE) Q5.1(GATE) R48.2 R54.2
N16674941: C79.2 Q14.3(GS) R103.1 R541.2
N16677707: C80.2 Q15.3(GS) R104.1 R542.1
N16765027: C102.2 R140.1 U10.1(VDD1)
N16765075: C101.1 R140.2 R545.2
N16767690: C103.2 R139.1 U10.16(VDD2)
N16833658: R141.1 U10.2(A1)
N16833676: R143.1 U10.3(A2)
N16833742: R145.1 U10.4(A3)
N16833760: R147.1 U10.5(A4)
N16833940: R142.1 U10.15(B1)
N16833942: R144.1 U10.14(B2)
N16834016: R146.1 U10.13(B3)
N16834018: R148.1 U10.12(B4)
N17093919: R2.2 R3.1
N17093922: R1.2 R2.1
N17243036: C284.2 Q61.1(B) R5.1 R8.1
N17244938: R15.2 R16.1
N17244999: R14.2 R15.1
N17245029: R20.2 R21.1
N17245032: R21.2 R22.1
N17252696: C30.1 R62.1 U103.2(VIN+)
N17252758: C29.2 R573.2 U103.1(VDD1)
N17252921: C27.2 R574.2 U103.8(VDD2)
N17253061: R63.2 U103.7(VOUT+)
N17253066: R64.2 U103.6(VOUT-)
N17253305: C28.2 R63.1 R537.1 U2.5(+IN)
N17253318: C31.1 R64.1 R65.2 U2.6(-IN)
N17253751: C26.2 R572.2 U2.8(V+)
N17259772: R30.1 R37.2
N17259775: R37.1 R39.2
N17259778: R39.1 R43.2
N17259967: R38.1 R40.2
N17259969: R40.1 R45.2
N17264035: C76.2 Q12.3(GS) R99.1 R543.2
N17264090: C77.2 Q13.3(GS) R100.1 R544.1
N17266948: R114.2 R115.1
N17266951: R115.2 R118.1
N17268549: C82.2 C83.2 R116.2 R117.1 U3.5(+IN)
N17268684: D8.1 R116.1 U3.7(OUT)
N17268693: C83.1 C87.2 R122.1 R123.1 U3.6(-IN)
N17268930: C248.2 R582.1 U3.8(V+)
N17268988: C92.1 C97.2 R127.2 R129.2 R134.1 U3.3(+IN)
N17269030: C97.1 C99.2 R138.1 U3.2(-IN)
N17269076: D8.2 R127.1 U3.1(OUT)
N17269867: C89.1 R120.1 R121.2
N17269877: C90.1 C91.1 R119.2 R121.1 U4.5(+IN)
N17270011: C91.2 C94.1 C96.1 R130.1 R132.1 U4.6(-IN)
N17270029: R130.2 R135.1
N17270191: C84.2 R583.1 U4.8(V+)
N17272262: R128.1 R136.2 U9.1(REF)
N17277038: T1.3(LR_SEC_2) T1.5(CR_SEC_2) T1.6(CR_SEC_1)
N17288635: C35.1 R67.1 R251.2 U5.1(VIA)
N17288650: C36.1 R68.1 R250.2 U5.2(VIB)
N17289174: C39.1 C40.1 R575.2 U5.3(VDDII) U5.8(VDDI)
N17289191: R69.1 U5.5(DISABLE)
N17289200: R70.1 U5.6(DT)
N17289613: C33.1 C497.1 R576.1 U5.16(VDDA)
N17289747: C38.1 R577.1 U5.11(VDDB)
N17291315: C46.1 R581.1 U106.5(VCC2)
N17329322: C245.1 U30.5(C1+)
N17329326: C245.2 U30.3(C1-)
N17381506: R27.2 R216.1
N17381622: R52.2 R218.1
N17381677: R51.2 R219.1
N17452823: C136.2 C142.1 U15.6(COM)
N17452839: C139.1 C140.1 R181.1 U15.1(+VIN)
N17452887: C159.1 C160.1 R183.1 U18.1(+VIN)
N17453218: C152.1 C161.1 R182.1 U17.1(+VIN)
N17453412: C205.1 C207.1 R188.1 U23.1(+VIN)
N17453587: C196.1 C197.1 R187.1 U22.1(+VIN)
N17453815: C212.1 C213.1 R189.1 U24.1(+VIN)
N17454032: C183.1 C184.1 R186.1 U21.1(+VIN)
N17454238: C174.1 C175.1 R184.1 U19.1(+VIN)
N17454469: C179.1 C180.1 R185.1 U20.1(+VIN)
N17461429: C281.1 R244.1 R245.2 U34.2(-IN) U34.5(+IN)
N17461431: C278.2 R240.1 R243.1 U34.3(+IN)
N17461459: C280.1 R241.2 R242.1 U34.6(-IN)
N17461635: C279.1 R239.2 R596.2 U34.8(V+)
N17461650: C282.2 Q60.1(B) R239.1 U34.1(OUT) U34.7(OUT)
N17461720: Q60.2(E) U35.3(VF-)
N17461740: R246.2 U35.2(VF+)
N17461769: R247.1 U35.7(VB)
N17461771: C612.1 R247.2 R597.1 U35.8(VCC)
N17461781: R248.2 U35.6(VO)
N17577735: R538.1 R539.2 U55.1(REF)
N17603041: T1.12(LR_PRI_1) T1.13(CR_PRI_2) T1.14(CR_PRI_1)
N17746491: C530.1 C531.1 R578.2 U104.1(VCC1)
N17747250: C43.1 R71.2 R72.1 U104.2(IN+)
N17749975: C47.1 C48.1 R579.2 U106.1(VCC1)
N17750019: C44.1 R73.1 R74.2 U106.2(IN+)
N17751858: C41.1 C498.1 R580.1 U104.5(VCC2)
N17785545: C532.1 C533.1 R584.2 U108.1(VCC1)
N17785579: C544.1 R550.1 R551.2 U108.2(IN+)
N17785699: C540.1 C541.1 R585.2 U107.1(VCC1)
N17785727: C543.1 R548.1 R549.2 U107.2(IN+)
N17785767: C536.1 C542.1 R591.1 U108.5(VCC2)
N17785926: C545.1 C549.1 R590.1 U107.5(VCC2)
N17788175: C550.1 C551.1 R586.2 U110.1(VCC1)
N17788213: C558.1 R554.1 R555.2 U110.2(IN+)
N17788281: C554.1 C555.1 R587.2 U109.1(VCC1)
N17788301: C557.1 R552.1 R553.2 U109.2(IN+)
N17788345: C553.1 C556.1 R589.1 U110.5(VCC2)
N17788478: C559.1 C563.1 R588.1 U109.5(VCC2)
N17790300: C564.1 C565.1 R598.2 U112.1(VCC1)
N17790352: C572.1 R558.1 R559.2 U112.2(IN+)
N17790406: C568.1 C569.1 R599.2 U111.1(VCC1)
N17790440: C571.1 R556.1 R557.2 U111.2(IN+)
N17790484: C567.1 C570.1 R592.1 U112.5(VCC2)
N17790617: C573.1 C577.1 R593.1 U111.5(VCC2)
N17792648: C578.1 C579.1 R600.2 U114.1(VCC1)
N17792696: C586.1 R562.2 R563.1 U114.2(IN+)
N17792742: C582.1 C583.1 R601.2 U113.1(VCC1)
N17792776: C585.1 R560.1 R561.2 U113.2(IN+)
N17792812: C581.1 C584.1 R594.1 U114.5(VCC2)
N17792937: C587.1 C591.1 R595.1 U113.5(VCC2)
N17799215: D58.1(ANODE) R565.1
N17799359: D60.1(ANODE) R567.1
N17812200: CT12.1 D61.3(A)
N17812202: CT11.1 D62.3(A)
N17820985: R569.1 R571.2
N17820987: R569.2 R570.1
N17880901: D57.1(ANODE) R564.2
N17880973: D59.1(ANODE) R566.2
N17943029: R28.2 R217.1
